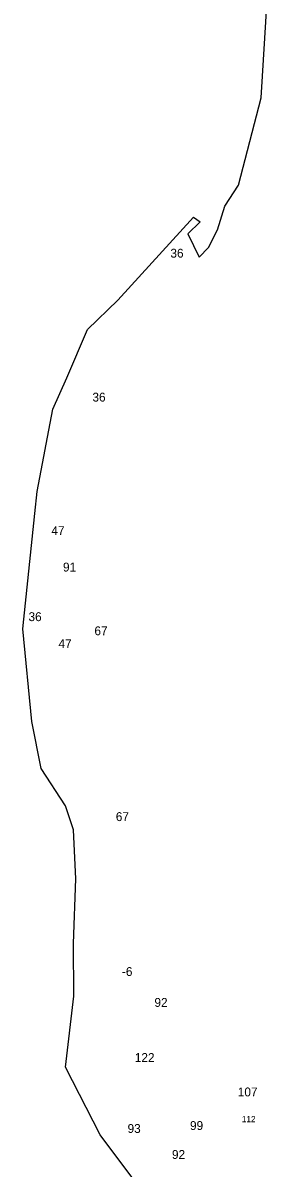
# Model space of a CAD drawing. Extents: x -782710 to -781421, y -973233 to -970222.
# Drawn here: x -782710 to -782551, y -971729 to -970985 of the extents above; entities that cross this region are included whole.
import ezdxf

# ---------------------------------------------------------------- set-up
doc = ezdxf.new("R2010")
doc.units = 0
doc.layers.add('Vrstva 13', color=7, linetype='Continuous')
doc.layers.add('Vrstva 24', color=7, linetype='Continuous')

msp = doc.modelspace()

# ---------------------------------------------------------------- linework, layer by layer
at = {"layer": 'Vrstva 13'}
for p, q in [((-782554.45, -971033.72), (-782550.57, -970969.92)), ((-782569.24, -971090.43), (-782554.45, -971033.72)), ((-782578.17, -971104.05), (-782569.24, -971090.43)), ((-782582.96, -971119.38), (-782578.17, -971104.05)), ((-782647.69, -971165.13), (-782598.44, -971111.17)), ((-782598.44, -971111.17), (-782594.24, -971114.29)), ((-782594.24, -971114.29), (-782602.11, -971122.06)), ((-782588.7, -971130.97), (-782582.96, -971119.38)), ((-782602.11, -971122.06), (-782594.87, -971137.15)), ((-782594.87, -971137.15), (-782588.7, -971130.97)), ((-782667.42, -971184.18), (-782647.69, -971165.13)), ((-782680.88, -971215.57), (-782667.42, -971184.18)), ((-782690.03, -971236), (-782680.88, -971215.57)), ((-782700.24, -971289.42), (-782690.03, -971236)), ((-782701.73, -971303.68), (-782700.24, -971289.42)), ((-782709.6, -971378.7), (-782701.73, -971303.68)), ((-782703.81, -971438.88), (-782709.6, -971378.7)), ((-782697.69, -971469.48), (-782703.81, -971438.88)), ((-782681.79, -971493.68), (-782697.69, -971469.48)), ((-782676.64, -971509.16), (-782681.79, -971493.68)), ((-782675.15, -971540.98), (-782676.64, -971509.16)), ((-782676.65, -971583), (-782675.15, -971540.98)), ((-782676.43, -971617.37), (-782676.65, -971583)), ((-782681.74, -971663.34), (-782676.43, -971617.37)), ((-782659.3, -971707.4), (-782681.74, -971663.34)), ((-782632.07, -971743.47), (-782659.3, -971707.4))]:
    msp.add_line(p, q, dxfattribs=at)

# ---------------------------------------------------------------- texts
at = {"layer": 'Vrstva 24'}
for s, height, p in [('36', 5.76, (-782613.546, -971137.492)), ('36', 5.76, (-782664.316, -971231.012)), ('47', 5.76, (-782691.041, -971317.722)), ('91', 5.76, (-782683.489, -971341.412)), ('36', 5.76, (-782705.926, -971373.652)), ('67', 5.76, (-782663.018, -971382.832)), ('47', 5.76, (-782686.391, -971391.162)), ('67', 5.76, (-782649.088, -971503.552)), ('-6', 5.76, (-782645.103, -971604.2)), ('92', 5.76, (-782623.936, -971624.272)), ('122', 5.76, (-782636.715, -971660.072)), ('107', 5.76, (-782569.684, -971682.422)), ('99', 5.76, (-782600.799, -971704.262)), ('112', 4, (-782567.036, -971699.18)), ('93', 5.76, (-782641.446, -971706.182)), ('92', 5.76, (-782612.546, -971723.052))]:
    msp.add_text(s, height=height, dxfattribs=at).set_placement(p)

doc.saveas('drawing.dxf')
